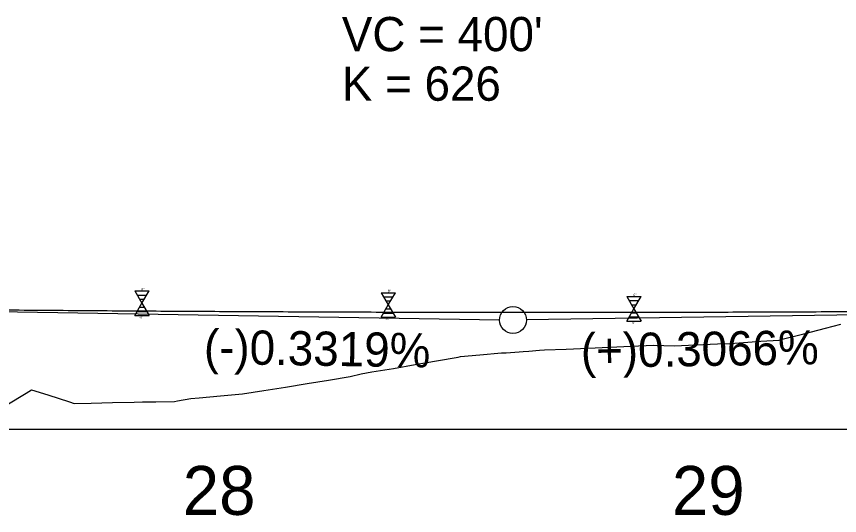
# Model space of a CAD drawing. Extents: x 573468 to 580768, y -57414 to -51768.
# Drawn here: x 575529.9 to 575698.2, y -53423 to -53320.9 of the extents above; entities that cross this region are included whole.
import ezdxf

# ---------------------------------------------------------------- set-up
doc = ezdxf.new("R2010")
doc.units = 0
for name, color, linetype in [('Exist Profile Cell', 7, 'Continuous'), ('Exist Vertical Profile Ground Line', 7, 'Continuous'), ('Exist Vertical Profile Horizontal Axis Label Major', 7, 'Continuous'), ('Pattern 2', 7, 'Continuous'), ('Prop Vertical Profile Curve Label', 7, 'Continuous'), ('Prop Vertical Profile Grade', 7, 'Continuous'), ('Prop Vertical Profile Grade Label', 7, 'Continuous'), ('Prop VPI Label', 7, 'Continuous')]:
    doc.layers.add(name, color=color, linetype=linetype)

msp = doc.modelspace()

# ---------------------------------------------------------------- linework, layer by layer
at = {"layer": 'Exist Profile Cell'}
msp.add_line((573502.62, -53405.32), (576177.52, -53405.32), dxfattribs=at)
at = {"layer": 'Exist Vertical Profile Ground Line'}
msp.add_lwpolyline([(575527.89, -53400.34), (575531.87, -53397.91), (575532.98, -53397.23), (575536.29, -53398.29), (575540.71, -53399.69), (575541.69, -53400.01), (575545.13, -53399.95), (575549.55, -53399.87), (575553.96, -53399.76), (575555.69, -53399.71), (575558.38, -53399.67), (575562.18, -53399.6), (575562.8, -53399.5), (575565.53, -53399.02), (575567.22, -53398.87), (575571.64, -53398.46), (575576.08, -53398.03), (575580.47, -53397.36), (575584.89, -53396.68), (575589.31, -53395.97), (575593.73, -53395.25), (575598.15, -53394.49), (575600.4, -53393.95), (575602.56, -53393.59), (575606.98, -53392.85), (575611.4, -53392.09), (575615.82, -53391.32), (575620.24, -53390.53), (575620.67, -53390.45), (575624.65, -53390.09), (575629.07, -53389.7), (575630.03, -53389.67), (575632.68, -53389.44), (575633.49, -53389.4), (575634.67, -53389.34), (575636.83, -53389.13), (575637.91, -53389.09), (575642.33, -53388.91), (575646.74, -53388.72), (575651.16, -53388.53), (575655.58, -53388.32), (575660.19, -53388.1), (575664.43, -53388.24), (575668.83, -53388.05), (575673.25, -53387.86), (575675.83, -53387.74), (575677.67, -53387.62), (575682.09, -53387.32), (575685.85, -53387.07), (575686.51, -53386.9), (575690.92, -53385.77), (575695.34, -53384.64), (575698.48, -53383.83)], dxfattribs=at)
at = {"layer": 'Pattern 2'}
for p, q in [((575554.08, -53377.02), (575557.01, -53377.02)), ((575554.08, -53377.02), (575555.55, -53379.52)), ((575554.57, -53377.85), (575556.53, -53377.85)), ((575555.55, -53379.52), (575557.01, -53377.02)), ((575604.45, -53377.37), (575607.38, -53377.37)), ((575604.45, -53377.37), (575605.92, -53379.87)), ((575605.92, -53379.87), (575607.38, -53377.37)), ((575554.08, -53382.02), (575555.55, -53379.52)), ((575555.06, -53378.69), (575556.04, -53378.69)), ((575555.55, -53379.52), (575557.01, -53382.02)), ((575604.94, -53378.2), (575606.9, -53378.2)), ((575605.43, -53379.04), (575606.41, -53379.04)), ((575654.7, -53378.17), (575657.63, -53378.17)), ((575654.7, -53378.17), (575656.17, -53380.67)), ((575655.19, -53379), (575657.15, -53379)), ((575656.17, -53380.67), (575657.63, -53378.17)), ((575554.57, -53381.19), (575556.53, -53381.19)), ((575555.06, -53380.35), (575556.04, -53380.35)), ((575604.45, -53382.37), (575605.92, -53379.87)), ((575605.43, -53380.7), (575606.41, -53380.7)), ((575605.92, -53379.87), (575607.38, -53382.37)), ((575654.7, -53383.17), (575656.17, -53380.67)), ((575655.68, -53379.84), (575656.66, -53379.84)), ((575656.17, -53380.67), (575657.63, -53383.17)), ((575554.08, -53382.02), (575557.01, -53382.02)), ((575604.45, -53382.37), (575607.38, -53382.37)), ((575604.94, -53381.54), (575606.9, -53381.54)), ((575655.19, -53382.34), (575657.15, -53382.34)), ((575655.68, -53381.5), (575656.66, -53381.5)), ((575654.7, -53383.17), (575657.63, -53383.17))]:
    msp.add_line(p, q, dxfattribs=at)
at = {"layer": 'Prop Vertical Profile Grade'}
msp.add_spline([(575431.43, -53379.65), (575439.43, -53379.78), (575447.43, -53379.91), (575455.43, -53380.03), (575463.43, -53380.14), (575471.43, -53380.25), (575479.43, -53380.36), (575487.43, -53380.46), (575495.43, -53380.55), (575503.43, -53380.64), (575511.43, -53380.72), (575519.43, -53380.8), (575527.43, -53380.88), (575535.43, -53380.95), (575543.43, -53381.01), (575551.43, -53381.07), (575559.43, -53381.12), (575567.43, -53381.17), (575575.43, -53381.21), (575583.43, -53381.25), (575591.43, -53381.28), (575599.43, -53381.31), (575607.43, -53381.34), (575615.43, -53381.35), (575623.43, -53381.37), (575631.43, -53381.37), (575639.43, -53381.38), (575647.43, -53381.37), (575655.43, -53381.37), (575663.43, -53381.35), (575671.43, -53381.34), (575679.43, -53381.31), (575687.43, -53381.28), (575695.43, -53381.25), (575703.43, -53381.21), (575711.43, -53381.17), (575719.43, -53381.12), (575727.43, -53381.07), (575735.43, -53381.01), (575743.43, -53380.94), (575751.43, -53380.88), (575759.43, -53380.8), (575767.43, -53380.72), (575775.43, -53380.64), (575783.43, -53380.55), (575791.43, -53380.45), (575799.43, -53380.35), (575807.43, -53380.25), (575815.43, -53380.14), (575823.43, -53380.02), (575831.43, -53379.9)], degree=3, dxfattribs=at)
at = {"layer": 'Prop VPI Label'}
for p, q in [((575431.43, -53379.65), (575628.68, -53382.92)), ((575831.43, -53379.9), (575634.18, -53382.93))]:
    msp.add_line(p, q, dxfattribs=at)
msp.add_circle((575631.43, -53382.97), 2.75, dxfattribs=at)

# ---------------------------------------------------------------- texts
at = {"layer": 'Exist Vertical Profile Horizontal Axis Label Major'}
for s, p in [('28', (575563.9, -53422.82)), ('29', (575663.94, -53422.82))]:
    msp.add_text(s, height=10, dxfattribs=at).set_placement(p)
at = {"layer": 'Pattern 2'}
for s, p in [('6"', (575555.44, -53376.92)), ('6"', (575605.81, -53377.27)), ('6"', (575656.06, -53378.07)), ('-6"', (575554.97, -53382.62)), ('-6"', (575605.34, -53382.97)), ('-6"', (575655.59, -53383.77))]:
    msp.add_text(s, height=0.5, rotation=360, dxfattribs=at).set_placement(p)
at = {"layer": 'Prop Vertical Profile Curve Label'}
for s, p in [("VC = 400'", (575596.43, -53327.97)), ('K = 626', (575596.43, -53338.11))]:
    msp.add_text(s, height=7, dxfattribs=at).set_placement(p)
at = {"layer": 'Prop Vertical Profile Grade Label'}
for s, rotation, p in [('(-)0.3319%', 359.0493, (575568.18, -53391.92)), ('(+)0.3066%', 0.8782, (575645.36, -53392.76))]:
    msp.add_text(s, height=7, rotation=rotation, dxfattribs=at).set_placement(p)

doc.saveas('drawing.dxf')
